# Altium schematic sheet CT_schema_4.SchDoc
size 218 x 258 mm
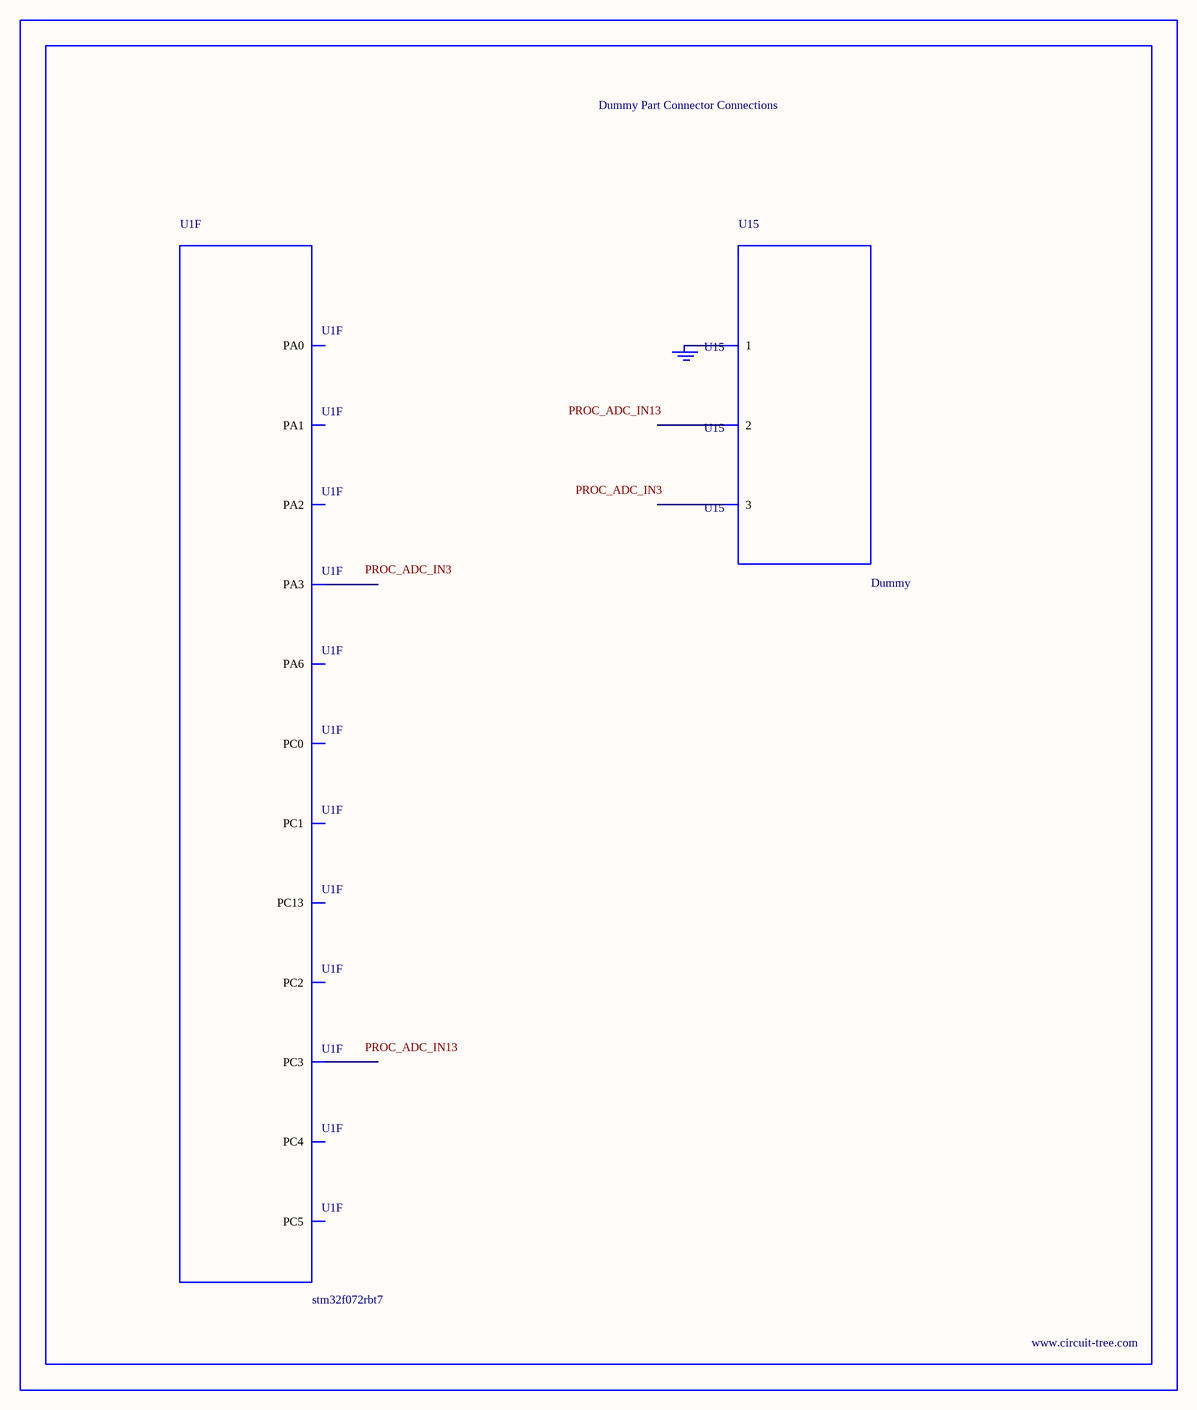
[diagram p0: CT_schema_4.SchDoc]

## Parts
BORDER3  (no value)
GND_INSTANCE_3_0  (no value)
U1  stm32f072rbt7  [LQFP64]  (part F of 6)
U15  Dummy  [DUMMY_PACKAGE_153]

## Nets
NetGND_INSTANCE_3_0_0: GND_INSTANCE_3_0.0(GND) U15.1

Not connected (* = marked no-connect by the designer): U1 2(PC13) 8(PC0) 9(PC1) 10(PC2) 11(PC3) 14(PA0) 15(PA1) 16(PA2) 17(PA3) 22(PA6) 24(PC4) 25(PC5); U15 2 3

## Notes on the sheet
- Labels drawn without touching a wire or pin: PROC_ADC_IN3, PROC_ADC_IN13

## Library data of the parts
BORDER3 = BORDER_PAGE3
GND_INSTANCE_3_0 = GND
